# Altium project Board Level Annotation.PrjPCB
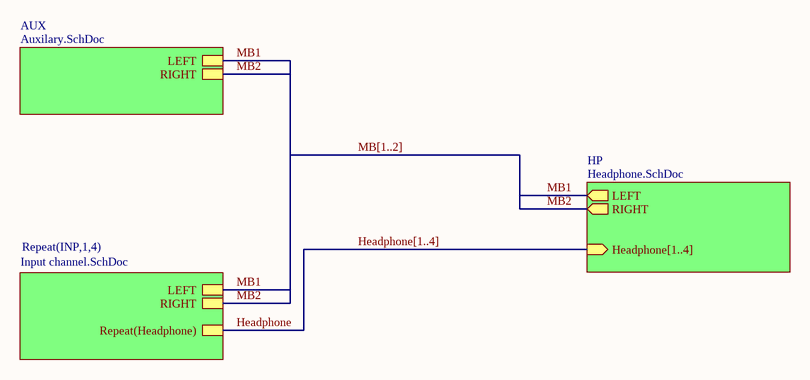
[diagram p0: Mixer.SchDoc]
4 sheets, 97 parts. Net scope: hierarchical (ports join the sheet entries above them; power ports are global).
Board file: Mixer Placed.PCBDOC
Sheets:
  Mixer.SchDoc
    AUX = Auxilary.SchDoc
    HP = Headphone.SchDoc
    INP1 = Input channel.SchDoc
    INP2 = Input channel.SchDoc
    INP3 = Input channel.SchDoc
    INP4 = Input channel.SchDoc

## Sheet Mixer.SchDoc: Board Level Annotation
size 431 x 279 mm; Organization: Altium Limited; Address1: L3, 12a Rodborough Rd; Address2: Frenchs Forest; Address3: NSW; Address4: Australia 2086; DocumentNumber: 5; SheetNumber: 5; SheetTotal: 8

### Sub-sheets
AUX = Auxilary.SchDoc: LEFT, RIGHT
HP = Headphone.SchDoc: Headphone[1..4] (in), LEFT (out), RIGHT (out)
Repeat(INP,1,4) = Input channel.SchDoc: LEFT, RIGHT, Repeat(Headphone)

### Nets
MB1: sheet AUX/LEFT, sheet HP/LEFT, sheet Repeat(INP,1,4)/LEFT  [project net LCHANNEL]
MB2: sheet AUX/RIGHT, sheet HP/RIGHT, sheet Repeat(INP,1,4)/RIGHT

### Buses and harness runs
bus Headphone[1..4] = sheet HP/Headphone[1..4]
bus MB[1..2]

## Sheet Auxilary.SchDoc: Board Level Annotation
size 431 x 279 mm; Organization: Altium Limited; Address1: L3, 12a Rodborough Rd; Address2: Frenchs Forest; Address3: NSW; Address4: Australia 2086; DocumentNumber: 1; SheetNumber: 1; SheetTotal: 8
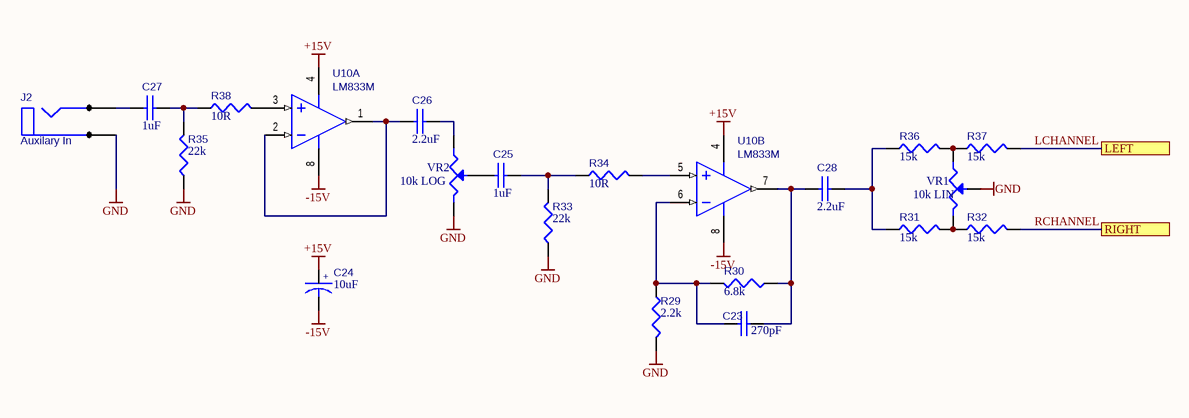
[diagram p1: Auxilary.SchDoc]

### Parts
C23  270pF  [RAD0.2]
C24  10uF  [RB.2/.4]
C25  1uF  [RB.2/.4-NP]
C26  2.2uF  [RB.2/.4-NP]
C27  1uF  [RB.2/.4-NP]
C28  2.2uF  [RB.2/.4-NP]
J2  Auxilary In  [JACK-6.25MM]
R29  2.2k  [AXIAL0.4]
R30  6.8k  [AXIAL0.4]
R31  15k  [AXIAL0.4]
R32  15k  [AXIAL0.4]
R33  22k  [AXIAL0.4]
R34  10R  [AXIAL0.4]
R35  22k  [AXIAL0.4]
R36  15k  [AXIAL0.4]
R37  15k  [AXIAL0.4]
R38  10R  [AXIAL0.4]
U10  LM833M  [DIP8]  (parts A,B of 2)
VR1  10k LIN  [POT - 24MM]
VR2  10k LOG  [POT - 24MM]

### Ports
LEFT, RIGHT

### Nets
+15V: C24.1 U10.4(V-)
-15V: C24.2 U10.8(V+)
GND: J2.3(C) R29.2 R33.1 R35.1 VR1.2(W) VR2.3
LCHANNEL: R37.2 ; port LEFT
RCHANNEL: R32.2 ; port RIGHT  [project net MB2]
NetC23_1: C23.1 R29.1 R30.2 U10.6(IN2-)
NetC23_2: C23.2 C28.1 R30.1 U10.7(OUT2)
NetC25_1: C25.1 VR2.2(W)
NetC25_2: C25.2 R33.2 R34.1
NetC26_1: C26.1 U10.1(OUT1) U10.2(IN1-)
NetC26_2: C26.2 VR2.1
NetC27_1: C27.1 J2.1(A)
NetC27_2: C27.2 R35.2 R38.1
NetC28_2: C28.2 R31.1 R36.1
NetR31_2: R31.2 R32.1 VR1.3
NetR34_2: R34.2 U10.5(IN2+)
NetR36_2: R36.2 R37.1 VR1.1
NetR38_2: R38.2 U10.3(IN1+)

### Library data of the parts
C23 C25-C28 = CAP: Capacitor
C24 = CAPACITOR POL: Bi-Polar Capacitor
J2 = PHONEJACK MONO
R29-R38 = RES1: Resistor
U10 = LM833M: Fast Settling Dual Operational Amplifier
VR1 VR2 = POT1: Potentiometer

## Sheet Headphone.SchDoc: Board Level Annotation
size 431 x 279 mm; Organization: Altium Limited; Address1: L3, 12a Rodborough Rd; Address2: Frenchs Forest; Address3: NSW; Address4: Australia 2086; DocumentNumber: 3; SheetNumber: 3; SheetTotal: 8
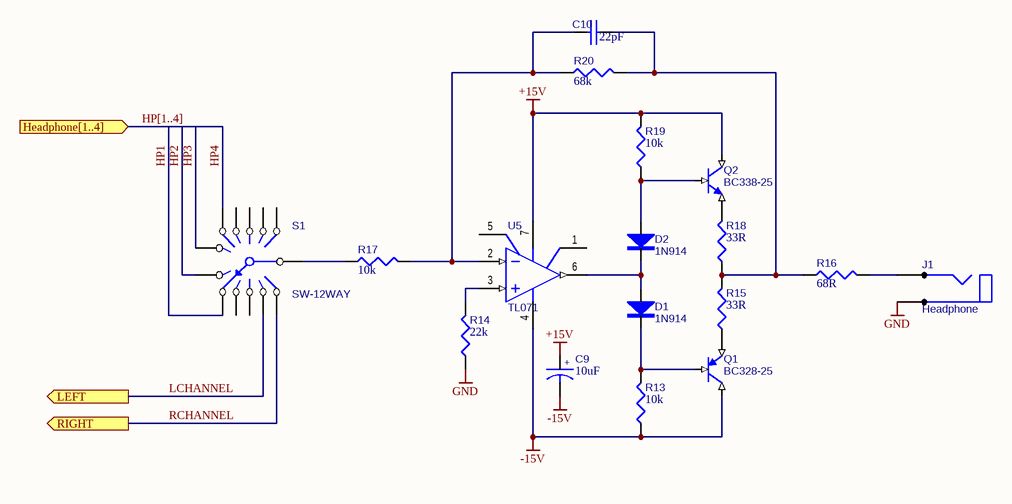
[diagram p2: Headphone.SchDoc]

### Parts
C9  10uF  [RB.2/.4]
C10  22pF  [RAD0.2]
D1  1N914  [DIODE0.4]
D2  1N914  [DIODE0.4]
J1  Headphone  [JACK-6.25MM]
Q1  BC328-25  [TO-92A]
Q2  BC338-25  [TO-92A]
R13  10k  [AXIAL0.4]
R14  22k  [AXIAL0.4]
R15  33R  [AXIAL0.4]
R16  68R  [AXIAL0.4]
R17  10k  [AXIAL0.4]
R18  33R  [AXIAL0.4]
R19  10k  [AXIAL0.4]
R20  68k  [AXIAL0.4]
S1  SW-12WAY  [SW-12WAY]
U5  TL071  [DIP8]

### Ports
Headphone[1..4] (in), LEFT (out), RIGHT (out)

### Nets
+15V: C9.1 Q2.1(C) R19.2 U5.7(VCC+)
-15V: C9.2 Q1.1(C) R13.1 U5.4(VCC-)
GND: J1.3(C) R14.1
HP1: S1.8  [project net Headphone1]
HP2: S1.7  [project net Headphone2]
HP3: S1.6  [project net Headphone3]
HP4: S1.5  [project net Headphone4]
LCHANNEL: S1.11 ; port LEFT
RCHANNEL: S1.12 ; port RIGHT  [project net MB2]
NetC10_1: C10.1 R17.2 R20.1 U5.2(IN-)
NetC10_2: C10.2 R15.2 R16.1 R18.1 R20.2
NetD1_1: D1.1(A) D2.2(K) U5.6(OUT)
NetD1_2: D1.2(K) Q1.2(B) R13.2
NetD2_1: D2.1(A) Q2.2(B) R19.1
NetJ1_1: J1.1(A) R16.2
NetQ1_3: Q1.3(E) R15.1
NetQ2_3: Q2.3(E) R18.2
NetR14_2: R14.2 U5.3(IN+)
NetR17_1: R17.1 S1.13

Not connected (* = marked no-connect by the designer): S1 1 2 3 4 9 10; U5 1(N1/O.S.) 5(O.S._N2)

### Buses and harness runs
bus HP[1..4] = port Headphone[1..4]

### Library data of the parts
C9 = CAPACITOR POL: Bi-Polar Capacitor
C10 = CAP: Capacitor
D1 D2 = 1N914: Diode
J1 = PHONEJACK MONO
Q1 = BC328-25: PNP BJT
Q2 = BC338-25: NPN BJT
R13-R20 = RES1: Resistor
U5 = TL071: Low-Noise  JFET-Input Operational Amplifiers

## Sheet Input channel.SchDoc: Board Level Annotation
size 431 x 279 mm; Organization: Altium Limited; Address1: L3, 12a Rodborough Rd; Address2: Frenchs Forest; Address3: NSW; Address4: Australia 2086; DocumentNumber: 4; SheetNumber: 4; SheetTotal: 8
Used 4 times, as channels INP1, INP2, INP3, INP4. Parts and nets are listed once, with the designators drawn on the sheet.
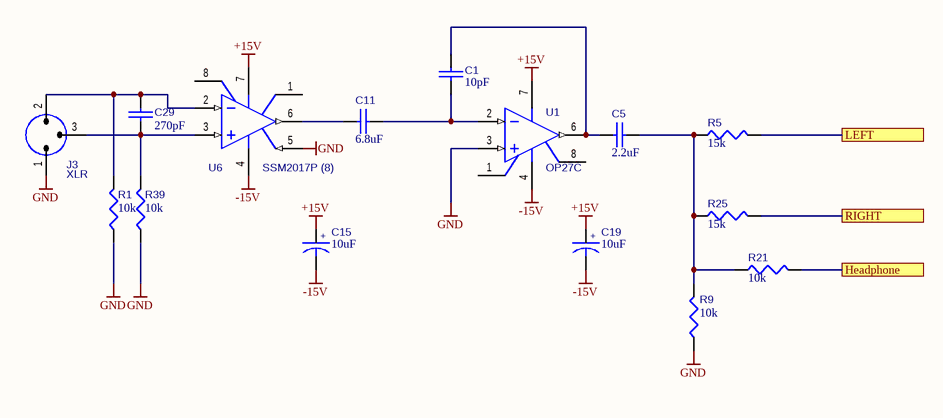
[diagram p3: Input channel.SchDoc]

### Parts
C1  10pF  [RAD0.2]
C5  2.2uF  [RB.2/.4-NP]
C11  6.8uF  [RB.2/.4-NP]
C15  10uF  [RB.2/.4]
C19  10uF  [RB.2/.4]
C29  270pF  [RAD0.2]
J3  XLR  [XLR-FEMALE]
R1  10k  [AXIAL0.4]
R5  15k  [AXIAL0.4]
R9  10k  [AXIAL0.4]
R21  10k  [AXIAL0.4]
R25  15k  [AXIAL0.4]
R39  10k  [AXIAL0.4]
U1  OP27C  [DIP8]
U6  SSM2017P (8)  [DIP8]

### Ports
Headphone, LEFT, RIGHT

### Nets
+15V: C15.1 C19.1 U1.7(V+) U6.7(V+)
-15V: C15.2 C19.2 U1.4(V-) U6.4(V-)
GND: J3.1 R1.1 R9.1 R39.1 U1.3(+IN) U6.5(REF)
Headphone: R21.2 ; port Headphone
LEFT: R5.2 ; port LEFT
RIGHT: R25.2 ; port RIGHT
NetC1_1: C1.1 C11.2 U1.2(-IN)
NetC1_2: C1.2 C5.1 U1.6(OUT)
NetC5_2: C5.2 R5.1 R9.2 R21.1 R25.1
NetC11_1: C11.1 U6.6(OUT)
NetC29_1: C29.1 J3.2 R1.2 U6.2(IN-)
NetC29_2: C29.2 J3.3 R39.2 U6.3(IN+)

Not connected (* = marked no-connect by the designer): U1 1(TRIM) 8(TRIM); U6 1(RG1) 8(RG2)

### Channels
INP1: designators C1=C4 C5=C8 C11=C14 C15=C18 C19=C22 C29=C32 J3=J6 R1=R4 R5=R8 R9=R12 R21=R24 R25=R28 R39=R42 U1=U4 U6=U9; ports Headphone=Headphone1 LEFT=LCHANNEL RIGHT=MB2
INP2: designators C1=C3 C5=C7 C11=C13 C15=C17 C19=C21 C29=C31 J3=J5 R1=R3 R5=R7 R9=R11 R21=R23 R25=R27 R39=R41 U1=U3 U6=U8; ports Headphone=Headphone2 LEFT=LCHANNEL RIGHT=MB2
INP3: designators C1=C2 C5=C6 C11=C12 C15=C16 C19=C20 C29=C30 J3=J4 R1=R2 R5=R6 R9=R10 R21=R22 R25=R26 R39=R40 U1=U2 U6=U7; ports Headphone=Headphone3 LEFT=LCHANNEL RIGHT=MB2
INP4: ports Headphone=Headphone4 LEFT=LCHANNEL RIGHT=MB2

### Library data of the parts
C1 C5 C11 C29 = CAP: Capacitor
C15 C19 = CAPACITOR POL: Bi-Polar Capacitor
J3 = XLR: XLR connector, PCB mounted
R1 R5 R9 R21 R25 R39 = RES1: Resistor
U1 = OP27C: Low Noise, High Speed Precision Operational Amplifier
U6 = SSM2017P (8): Self-Contained Audio Preamplifier

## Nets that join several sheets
+15V: Auxilary (C24.1 U10.4), Headphone (C9.1 Q2.1 R19.2 U5.7), INP1 (C18.1 C22.1 U4.7 U9.7), INP2 (C17.1 C21.1 U3.7 U8.7), INP3 (C16.1 C20.1 U2.7 U7.7), INP4 (C15.1 C19.1 U1.7 U6.7)
-15V: Auxilary (C24.2 U10.8), Headphone (C9.2 Q1.1 R13.1 U5.4), INP1 (C18.2 C22.2 U4.4 U9.4), INP2 (C17.2 C21.2 U3.4 U8.4), INP3 (C16.2 C20.2 U2.4 U7.4), INP4 (C15.2 C19.2 U1.4 U6.4)
GND: Auxilary (6 pins), Headphone (J1.3 R14.1), INP1 (6 pins), INP2 (6 pins), INP3 (6 pins), INP4 (6 pins)
Headphone1: Headphone (S1.8), INP1 (R24.2)
Headphone2: Headphone (S1.7), INP2 (R23.2)
Headphone3: Headphone (S1.6), INP3 (R22.2)
Headphone4: Headphone (S1.5), INP4 (R21.2)
LCHANNEL: Auxilary (R37.2), Headphone (S1.11), INP1 (R8.2), INP2 (R7.2), INP3 (R6.2), INP4 (R5.2)
MB2: Auxilary (R32.2), Headphone (S1.12), INP1 (R28.2), INP2 (R27.2), INP3 (R26.2), INP4 (R25.2)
